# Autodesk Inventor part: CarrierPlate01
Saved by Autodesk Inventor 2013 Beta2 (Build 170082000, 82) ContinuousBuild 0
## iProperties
Created: 2008-02
Part Number: CarrierPlate01
Document SubType Name: Modeling
Designer: grh
Density: 1 g/cm^3
Material: Generic
Author: grh
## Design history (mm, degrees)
sketch "Sketch1"
  geometry: L1 (48.514, 0)-(0, 0); C1 r 53.34 at (0, 0)
  constraints: 2 end point, 1 centre point, 1 horizontal, 1 other
  dimensions: "BlankDiameter" = 106.68 diameter of C1; "PlanetRadius" = 48.514 distance of L1.start L1.end
extrude "Extrusion1" new body sketch "Sketch1" stored distance "d9" = 13.97; taper "d10" = 0 deg
node "Axis1"
node "Axis2"
body "Solid1"
